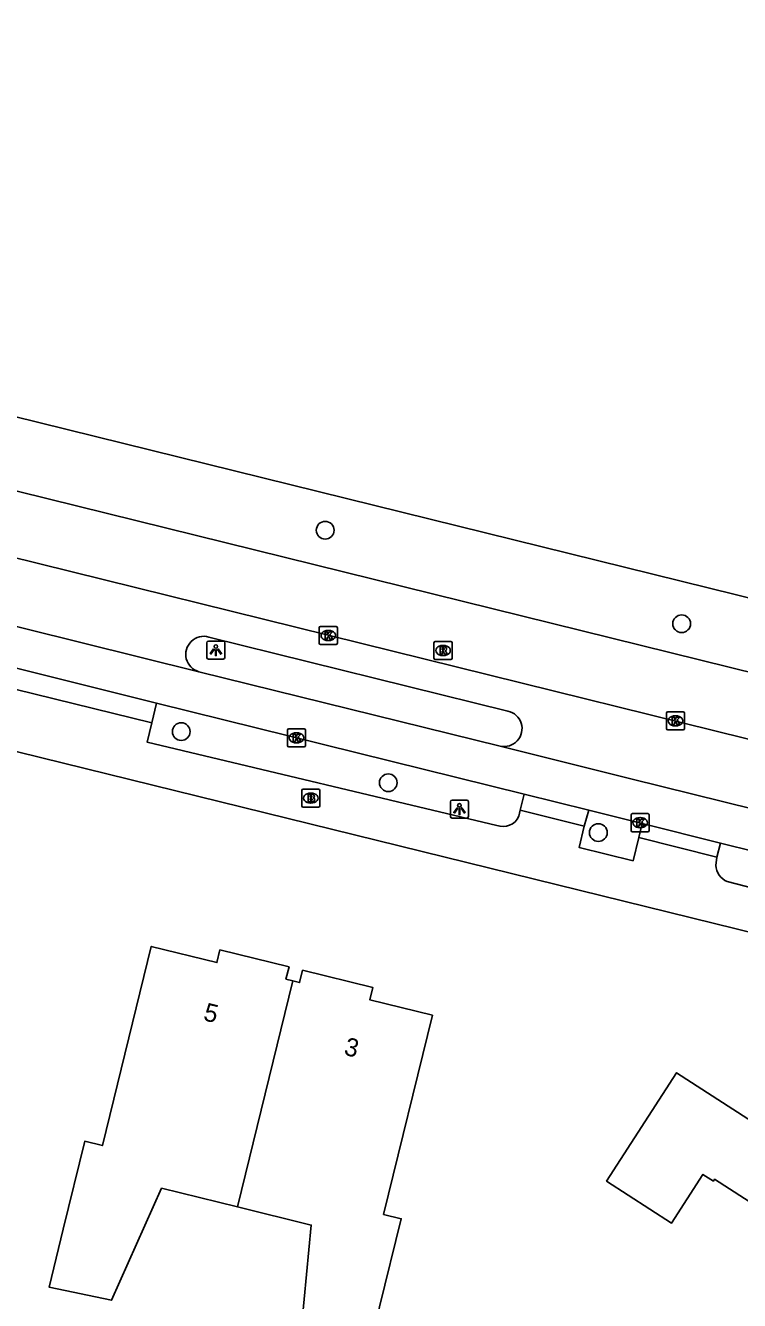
# Model space of a CAD drawing. Extents: x 161141 to 161601, y 381708 to 382245.
# Drawn here: x 161505.4 to 161544.8, y 382126.6 to 382197 of the extents above; entities that cross this region are included whole.
import ezdxf

# ---------------------------------------------------------------- set-up
doc = ezdxf.new("R2010")
doc.units = 0
for name, color, linetype in [('IMGEO_Boom', 7, 'Continuous'), ('IMGEO_Brandkraan', 7, 'Continuous'), ('IMGEO_Fietspad_gesloten', 7, 'Continuous'), ('IMGEO_Kolk', 7, 'Continuous'), ('IMGEO_Lichtpunt', 7, 'Continuous'), ('IMGEO_Pand', 7, 'Continuous'), ('IMGEO_Pand_nummerreeks', 7, 'Continuous'), ('IMGEO_Parkeervlak_open', 7, 'Continuous'), ('IMGEO_Rijbaan_lokaal_gesloten', 7, 'Continuous'), ('IMGEO_Rioolput', 7, 'Continuous'), ('IMGEO_Voetpad_open', 7, 'Continuous')]:
    doc.layers.add(name, color=color, linetype=linetype)

msp = doc.modelspace()

# ---------------------------------------------------------------- linework, layer by layer
at = {"layer": 'IMGEO_Boom'}
for centre in [(161521.926, 382169.098), (161541.602, 382163.938), (161513.981, 382157.98), (161525.411, 382155.161), (161537.002, 382152.408)]:
    msp.add_circle(centre, 0.489, dxfattribs=at)
at = {"layer": 'IMGEO_Brandkraan'}
for p, q in [((161520.632, 382153.886), (161520.632, 382154.738)), ((161520.707, 382154.812), (161521.559, 382154.812)), ((161521.633, 382154.738), (161521.633, 382153.886)), ((161521.143, 382154.032), (161521.118, 382154.032)), ((161521.12, 382154.592), (161521.145, 382154.592)), ((161521.559, 382153.812), (161520.707, 382153.812))]:
    msp.add_line(p, q, dxfattribs=at)
for points in [[(161520.632, 382153.886), (161520.632, 382154.738)], [(161520.707, 382154.812), (161521.559, 382154.812)], [(161521.633, 382154.738), (161521.633, 382153.886)], [(161520.98, 382154.512), (161520.98, 382154.112), (161521.193, 382154.112)], [(161521.211, 382154.512), (161520.98, 382154.512)], [(161521.159, 382154.431), (161521.105, 382154.431), (161521.105, 382154.355)], [(161521.105, 382154.355), (161521.158, 382154.355)], [(161521.167, 382154.279), (161521.105, 382154.279), (161521.105, 382154.198)], [(161521.105, 382154.198), (161521.167, 382154.198)], [(161521.559, 382153.812), (161520.707, 382153.812)]]:
    msp.add_lwpolyline(points, dxfattribs=at)
for centre, radius, start, end in [((161520.709, 382154.736), 0.0765, 91.55205, 178.44795), ((161520.709, 382154.736), 0.0765, 91.55205, 178.44795), ((161521.557, 382154.736), 0.0765, 1.55205, 88.44795), ((161521.557, 382154.736), 0.0765, 1.55205, 88.44795), ((161521.16, 382154.393), 0.0379, 267.82845, 90.93552), ((161521.168, 382154.238), 0.0404, 269.87594, 90.50774), ((161521.199, 382154.363), 0.251, 268.66757, 293.53466), ((161521.215, 382154.367), 0.145, 59.4692, 91.53667), ((161521.24, 382154.414), 0.0922, 285.51372, 58.15012), ((161521.245, 382154.222), 0.105, 301.31148, 78.98903), ((161520.709, 382153.888), 0.0765, 181.55205, 268.44795), ((161520.709, 382153.888), 0.0765, 181.55205, 268.44795), ((161521.557, 382153.888), 0.0765, 271.55205, 358.44795), ((161521.557, 382153.888), 0.0765, 271.55205, 358.44795)]:
    msp.add_arc(centre, radius, start, end, dxfattribs=at)
for centre, major_axis, ratio, start_param, end_param in [((161521.119, 382154.312), (-0.387, 0.002), 0.722429, 4.712389, 7.853982), ((161521.144, 382154.312), (-0.39, 0.002), 0.717154, 1.570796, 4.712389)]:
    msp.add_ellipse(centre, major_axis=major_axis, ratio=ratio, start_param=start_param, end_param=end_param, dxfattribs=at)
at = {"layer": 'IMGEO_Fietspad_gesloten'}
for points in [[(161502.062, 382164.475), (161514.959, 382161.288)], [(161504.007, 382161.696), (161512.622, 382159.561)], [(161531.581, 382157.18), (161514.959, 382161.288)], [(161512.622, 382159.561), (161532.902, 382154.52)], [(161531.581, 382157.18), (161538.79, 382155.377), (161545.639, 382153.688), (161546.127, 382153.566)], [(161532.902, 382154.52), (161536.483, 382153.641)], [(161539.427, 382152.906), (161536.483, 382153.641)], [(161543.747, 382151.827), (161539.427, 382152.906)], [(161574.138, 382144.342), (161568.305, 382145.8), (161553.532, 382149.4), (161545.675, 382151.345), (161543.747, 382151.827)]]:
    msp.add_lwpolyline(points, dxfattribs=at)
at = {"layer": 'IMGEO_Kolk'}
for p, q in [((161521.599, 382162.863), (161521.599, 382163.715)), ((161521.674, 382163.789), (161522.526, 382163.789)), ((161522.087, 382163.569), (161522.112, 382163.569)), ((161522.6, 382163.715), (161522.6, 382162.863)), ((161522.526, 382162.789), (161521.674, 382162.789)), ((161522.11, 382163.009), (161522.085, 382163.009)), ((161540.756, 382158.151), (161540.756, 382159.003)), ((161540.831, 382159.077), (161541.683, 382159.077)), ((161541.757, 382159.003), (161541.757, 382158.151)), ((161541.267, 382158.297), (161541.242, 382158.297)), ((161541.244, 382158.857), (161541.269, 382158.857)), ((161519.841, 382157.214), (161519.841, 382158.066)), ((161519.916, 382158.14), (161520.768, 382158.14)), ((161520.329, 382157.92), (161520.354, 382157.92)), ((161520.842, 382158.066), (161520.842, 382157.214)), ((161541.683, 382158.077), (161540.831, 382158.077)), ((161520.768, 382157.14), (161519.916, 382157.14)), ((161520.352, 382157.36), (161520.327, 382157.36)), ((161538.81, 382152.527), (161538.81, 382153.379)), ((161538.885, 382153.453), (161539.737, 382153.453)), ((161539.811, 382153.379), (161539.811, 382152.527)), ((161539.321, 382152.673), (161539.296, 382152.673)), ((161539.298, 382153.233), (161539.323, 382153.233)), ((161539.737, 382152.453), (161538.885, 382152.453))]:
    msp.add_line(p, q, dxfattribs=at)
for points in [[(161521.599, 382162.863), (161521.599, 382163.715)], [(161521.674, 382163.789), (161522.526, 382163.789)], [(161521.92, 382163.489), (161522.043, 382163.489), (161522.043, 382163.338), (161522.173, 382163.489), (161522.337, 382163.489), (161522.191, 382163.338), (161522.344, 382163.089), (161522.192, 382163.089), (161522.107, 382163.253), (161522.043, 382163.186), (161522.043, 382163.089), (161521.92, 382163.089), (161521.92, 382163.489)], [(161522.6, 382163.715), (161522.6, 382162.863)], [(161522.526, 382162.789), (161521.674, 382162.789)], [(161540.756, 382158.151), (161540.756, 382159.003)], [(161540.831, 382159.077), (161541.683, 382159.077)], [(161541.757, 382159.003), (161541.757, 382158.151)], [(161541.077, 382158.777), (161541.2, 382158.777), (161541.2, 382158.626), (161541.33, 382158.777), (161541.494, 382158.777), (161541.348, 382158.626), (161541.501, 382158.377), (161541.349, 382158.377), (161541.264, 382158.541), (161541.2, 382158.474), (161541.2, 382158.377), (161541.077, 382158.377), (161541.077, 382158.777)], [(161519.841, 382157.214), (161519.841, 382158.066)], [(161519.916, 382158.14), (161520.768, 382158.14)], [(161520.162, 382157.84), (161520.285, 382157.84), (161520.285, 382157.689), (161520.415, 382157.84), (161520.579, 382157.84), (161520.433, 382157.689), (161520.586, 382157.44), (161520.434, 382157.44), (161520.349, 382157.604), (161520.285, 382157.537), (161520.285, 382157.44), (161520.162, 382157.44), (161520.162, 382157.84)], [(161520.842, 382158.066), (161520.842, 382157.214)], [(161541.683, 382158.077), (161540.831, 382158.077)], [(161520.768, 382157.14), (161519.916, 382157.14)], [(161538.81, 382152.527), (161538.81, 382153.379)], [(161538.885, 382153.453), (161539.737, 382153.453)], [(161539.811, 382153.379), (161539.811, 382152.527)], [(161539.131, 382153.153), (161539.254, 382153.153), (161539.254, 382153.002), (161539.384, 382153.153), (161539.548, 382153.153), (161539.402, 382153.002), (161539.555, 382152.753), (161539.403, 382152.753), (161539.318, 382152.917), (161539.254, 382152.85), (161539.254, 382152.753), (161539.131, 382152.753), (161539.131, 382153.153)], [(161539.737, 382152.453), (161538.885, 382152.453)]]:
    msp.add_lwpolyline(points, dxfattribs=at)
for centre, start, end in [((161521.676, 382163.713), 91.55205, 178.44795), ((161521.676, 382163.713), 91.55205, 178.44795), ((161522.524, 382163.713), 1.55205, 88.44795), ((161522.524, 382163.713), 1.55205, 88.44795), ((161521.676, 382162.865), 181.55205, 268.44795), ((161521.676, 382162.865), 181.55205, 268.44795), ((161522.524, 382162.865), 271.55205, 358.44795), ((161522.524, 382162.865), 271.55205, 358.44795), ((161540.833, 382159.001), 91.55205, 178.44795), ((161540.833, 382159.001), 91.55205, 178.44795), ((161541.681, 382159.001), 1.55205, 88.44795), ((161541.681, 382159.001), 1.55205, 88.44795), ((161519.918, 382158.064), 91.55205, 178.44795), ((161519.918, 382158.064), 91.55205, 178.44795), ((161520.766, 382158.064), 1.55205, 88.44795), ((161520.766, 382158.064), 1.55205, 88.44795), ((161540.833, 382158.153), 181.55205, 268.44795), ((161540.833, 382158.153), 181.55205, 268.44795), ((161541.681, 382158.153), 271.55205, 358.44795), ((161541.681, 382158.153), 271.55205, 358.44795), ((161519.918, 382157.216), 181.55205, 268.44795), ((161519.918, 382157.216), 181.55205, 268.44795), ((161520.766, 382157.216), 271.55205, 358.44795), ((161520.766, 382157.216), 271.55205, 358.44795), ((161538.887, 382153.377), 91.55205, 178.44795), ((161538.887, 382153.377), 91.55205, 178.44795), ((161539.735, 382153.377), 1.55205, 88.44795), ((161539.735, 382153.377), 1.55205, 88.44795), ((161538.887, 382152.529), 181.55205, 268.44795), ((161538.887, 382152.529), 181.55205, 268.44795), ((161539.735, 382152.529), 271.55205, 358.44795), ((161539.735, 382152.529), 271.55205, 358.44795)]:
    msp.add_arc(centre, 0.0765, start, end, dxfattribs=at)
for centre, major_axis, ratio, start_param, end_param in [((161522.086, 382163.289), (-0.387, 0.002), 0.722429, 4.712389, 7.853982), ((161522.111, 382163.289), (-0.39, 0.002), 0.717154, 1.570796, 4.712389), ((161541.243, 382158.577), (-0.387, 0.002), 0.722429, 4.712389, 7.853982), ((161541.268, 382158.577), (-0.39, 0.002), 0.717154, 1.570796, 4.712389), ((161520.328, 382157.64), (-0.387, 0.002), 0.722429, 4.712389, 7.853982), ((161520.353, 382157.64), (-0.39, 0.002), 0.717154, 1.570796, 4.712389), ((161539.297, 382152.953), (-0.387, 0.002), 0.722429, 4.712389, 7.853982), ((161539.322, 382152.953), (-0.39, 0.002), 0.717154, 1.570796, 4.712389)]:
    msp.add_ellipse(centre, major_axis=major_axis, ratio=ratio, start_param=start_param, end_param=end_param, dxfattribs=at)
at = {"layer": 'IMGEO_Lichtpunt'}
for p, q in [((161515.394, 382162.884), (161515.394, 382162.077)), ((161515.394, 382162.884), (161515.394, 382162.077)), ((161516.296, 382162.979), (161515.488, 382162.979)), ((161516.296, 382162.979), (161515.488, 382162.979)), ((161516.39, 382162.077), (161516.39, 382162.884)), ((161516.39, 382162.077), (161516.39, 382162.884)), ((161515.488, 382161.983), (161516.296, 382161.983)), ((161515.488, 382161.983), (161516.296, 382161.983)), ((161528.839, 382154.111), (161528.839, 382153.304)), ((161528.839, 382154.111), (161528.839, 382153.304)), ((161529.741, 382154.206), (161528.933, 382154.206)), ((161529.741, 382154.206), (161528.933, 382154.206)), ((161529.835, 382153.304), (161529.835, 382154.111)), ((161529.835, 382153.304), (161529.835, 382154.111)), ((161528.933, 382153.21), (161529.741, 382153.21)), ((161528.933, 382153.21), (161529.741, 382153.21))]:
    msp.add_line(p, q, dxfattribs=at)
for points in [[(161515.768, 382162.548), (161515.807, 382162.52), (161515.619, 382162.258), (161515.581, 382162.285), (161515.768, 382162.548)], [(161515.87, 382162.5), (161515.917, 382162.5), (161515.917, 382162.178), (161515.87, 382162.178), (161515.87, 382162.5)], [(161515.98, 382162.52), (161516.018, 382162.547), (161516.205, 382162.285), (161516.166, 382162.257), (161515.98, 382162.52)], [(161529.213, 382153.775), (161529.252, 382153.747), (161529.064, 382153.485), (161529.026, 382153.512), (161529.213, 382153.775)], [(161529.315, 382153.727), (161529.362, 382153.727), (161529.362, 382153.405), (161529.315, 382153.405), (161529.315, 382153.727)], [(161529.425, 382153.747), (161529.463, 382153.774), (161529.65, 382153.512), (161529.611, 382153.484), (161529.425, 382153.747)]]:
    msp.add_lwpolyline(points, dxfattribs=at)
for centre in [(161515.893, 382162.682), (161529.338, 382153.909)]:
    msp.add_circle(centre, 0.0994, dxfattribs=at)
for centre, start, end in [((161515.488, 382162.884), 90, 180), ((161515.488, 382162.884), 90, 180), ((161516.296, 382162.884), 0, 90), ((161516.296, 382162.884), 0, 90), ((161515.488, 382162.077), 180, 270), ((161515.488, 382162.077), 180, 270), ((161516.296, 382162.077), 270, 0), ((161516.296, 382162.077), 270, 360), ((161528.933, 382154.111), 90, 180), ((161528.933, 382154.111), 90, 180), ((161529.741, 382154.111), 0, 90), ((161529.741, 382154.111), 0, 90), ((161528.933, 382153.304), 180, 270), ((161528.933, 382153.304), 180, 270), ((161529.741, 382153.304), 270, 0), ((161529.741, 382153.304), 270, 360)]:
    msp.add_arc(centre, 0.0946, start, end, dxfattribs=at)
at = {"layer": 'IMGEO_Pand'}
for points in [[(161520.139, 382144.214), (161519.762, 382144.307), (161519.93, 382144.992), (161516.121, 382145.928), (161515.951, 382145.235), (161512.324, 382146.126), (161509.63, 382135.132), (161508.659, 382135.371), (161507.469, 382130.515), (161506.686, 382127.32), (161510.135, 382126.59), (161512.894, 382132.773), (161517.083, 382131.744)], [(161517.083, 382131.744), (161521.155, 382130.743), (161520.5, 382123.927), (161524.147, 382123.029), (161524.932, 382126.234), (161526.122, 382131.09), (161525.15, 382131.328), (161527.844, 382142.322), (161524.397, 382143.169), (161524.565, 382143.853), (161520.683, 382144.806), (161520.515, 382144.122), (161520.139, 382144.214)], [(161520.139, 382144.214), (161517.083, 382131.744)], [(161550.072, 382133.499), (161541.319, 382139.15), (161537.458, 382133.165), (161541.046, 382130.85), (161542.779, 382133.537), (161543.353, 382133.166), (161543.421, 382133.271), (161546.466, 382131.307), (161546.398, 382131.202), (161549.259, 382129.356), (161549.327, 382129.461), (161561.573, 382121.485)]]:
    msp.add_lwpolyline(points, dxfattribs=at)
at = {"layer": 'IMGEO_Parkeervlak_open'}
msp.add_lwpolyline([(161515.508, 382163.202), (161532.014, 382159.113)], dxfattribs=at)
for centre, radius, start, end in [((161515.229, 382162.246), 0.996, 73.72323, 254.26741), ((161531.802, 382158.145), 0.99, 257.0798, 77.66807)]:
    msp.add_arc(centre, radius, start, end, dxfattribs=at)
at = {"layer": 'IMGEO_Rijbaan_lokaal_gesloten'}
for points in [[(161417.456, 382196.964), (161420.058, 382196.306), (161460.894, 382186.197), (161500, 382176.547), (161558.491, 382162.113), (161560.838, 382161.565), (161562.428, 382161.253), (161571.347, 382159.936), (161575.364, 382159.517)], [(161416.542, 382193.184), (161418.72, 382192.635), (161459.898, 382182.379), (161500, 382172.465), (161568.862, 382155.44)], [(161571.771, 382151.019), (161502.587, 382168.125), (161500, 382168.766), (161459.102, 382178.908), (161420.449, 382188.487), (161415.442, 382189.785), (161412.878, 382190.505)]]:
    msp.add_lwpolyline(points, dxfattribs=at)
at = {"layer": 'IMGEO_Rioolput'}
for p, q in [((161527.931, 382162.034), (161527.931, 382162.886)), ((161528.006, 382162.96), (161528.858, 382162.96)), ((161528.419, 382162.74), (161528.444, 382162.74)), ((161528.932, 382162.886), (161528.932, 382162.034)), ((161528.858, 382161.96), (161528.006, 382161.96)), ((161528.442, 382162.18), (161528.417, 382162.18))]:
    msp.add_line(p, q, dxfattribs=at)
for points in [[(161527.931, 382162.034), (161527.931, 382162.886)], [(161528.006, 382162.96), (161528.858, 382162.96)], [(161528.52, 382162.658), (161528.268, 382162.66), (161528.268, 382162.26)], [(161528.446, 382162.579), (161528.392, 382162.579), (161528.392, 382162.498)], [(161528.392, 382162.498), (161528.444, 382162.498)], [(161528.932, 382162.886), (161528.932, 382162.034)], [(161528.858, 382161.96), (161528.006, 382161.96)], [(161528.268, 382162.26), (161528.392, 382162.26), (161528.392, 382162.422), (161528.403, 382162.422)], [(161528.45, 382162.393), (161528.521, 382162.26), (161528.661, 382162.26), (161528.596, 382162.386)]]:
    msp.add_lwpolyline(points, dxfattribs=at)
for centre, radius, start, end in [((161528.008, 382162.884), 0.0765, 91.55205, 178.44795), ((161528.008, 382162.884), 0.0765, 91.55205, 178.44795), ((161528.428, 382162.687), 0.19, 274.7715, 282.96867), ((161528.452, 382162.483), 0.0964, 77.00612, 93.18647), ((161528.466, 382162.54), 0.0378, 276.66336, 79.67722), ((161528.519, 382162.548), 0.109, 350.36119, 89.41601), ((161528.517, 382162.548), 0.112, 277.58423, 350.98172), ((161528.501, 382162.333), 0.108, 29.51342, 73.79051), ((161528.856, 382162.884), 0.0765, 1.55205, 88.44795), ((161528.856, 382162.884), 0.0765, 1.55205, 88.44795), ((161528.008, 382162.036), 0.0765, 181.55205, 268.44795), ((161528.008, 382162.036), 0.0765, 181.55205, 268.44795), ((161528.402, 382162.369), 0.0533, 26.02933, 88.69889), ((161528.856, 382162.036), 0.0765, 271.55205, 358.44795), ((161528.856, 382162.036), 0.0765, 271.55205, 358.44795)]:
    msp.add_arc(centre, radius, start, end, dxfattribs=at)
for centre, major_axis, ratio, start_param, end_param in [((161528.418, 382162.46), (-0.387, 0.002), 0.722429, 4.712389, 7.853982), ((161528.443, 382162.46), (-0.39, 0.002), 0.717154, 1.570796, 4.712389)]:
    msp.add_ellipse(centre, major_axis=major_axis, ratio=ratio, start_param=start_param, end_param=end_param, dxfattribs=at)
at = {"layer": 'IMGEO_Voetpad_open'}
for points in [[(161387.058, 382185.651), (161389.844, 382185.251), (161418.52, 382178.097), (161457.897, 382168.303), (161477.956, 382163.494), (161500, 382158.072), (161544.61, 382147.101), (161553.295, 382144.911), (161577.621, 382138.939), (161579.137, 382138.37)], [(161512.36, 382158.471), (161503.727, 382160.581)], [(161512.622, 382159.561), (161512.36, 382158.471)], [(161512.36, 382158.471), (161512.101, 382157.407), (161531.397, 382152.805)], [(161532.682, 382153.637), (161532.902, 382154.52)], [(161532.619, 382153.305), (161532.682, 382153.637)], [(161536.22, 382152.756), (161532.682, 382153.637)], [(161536.483, 382153.641), (161536.22, 382152.756)], [(161536.22, 382152.756), (161535.94, 382151.584), (161538.923, 382150.852), (161539.24, 382152.141)], [(161539.427, 382152.906), (161539.24, 382152.141)], [(161539.24, 382152.141), (161543.551, 382151.041)], [(161543.747, 382151.827), (161543.551, 382151.041)], [(161543.551, 382151.041), (161543.482, 382150.599)], [(161544.121, 382149.704), (161553.984, 382147.153), (161572.587, 382142.588)]]:
    msp.add_lwpolyline(points, dxfattribs=at)
for centre, radius, start, end in [((161531.749, 382153.687), 0.95, 248.23371, 336.27164), ((161544.511, 382150.658), 1.03, 183.27164, 247.77949)]:
    msp.add_arc(centre, radius, start, end, dxfattribs=at)

# ---------------------------------------------------------------- texts
at = {"layer": 'IMGEO_Pand_nummerreeks'}
for s, p in [('5', (161515.157, 382142.055)), ('3', (161522.917, 382140.153))]:
    msp.add_text(s, height=1, rotation=346.22813, dxfattribs=at).set_placement(p)

doc.saveas('drawing.dxf')
